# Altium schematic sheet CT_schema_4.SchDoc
size 395 x 205 mm
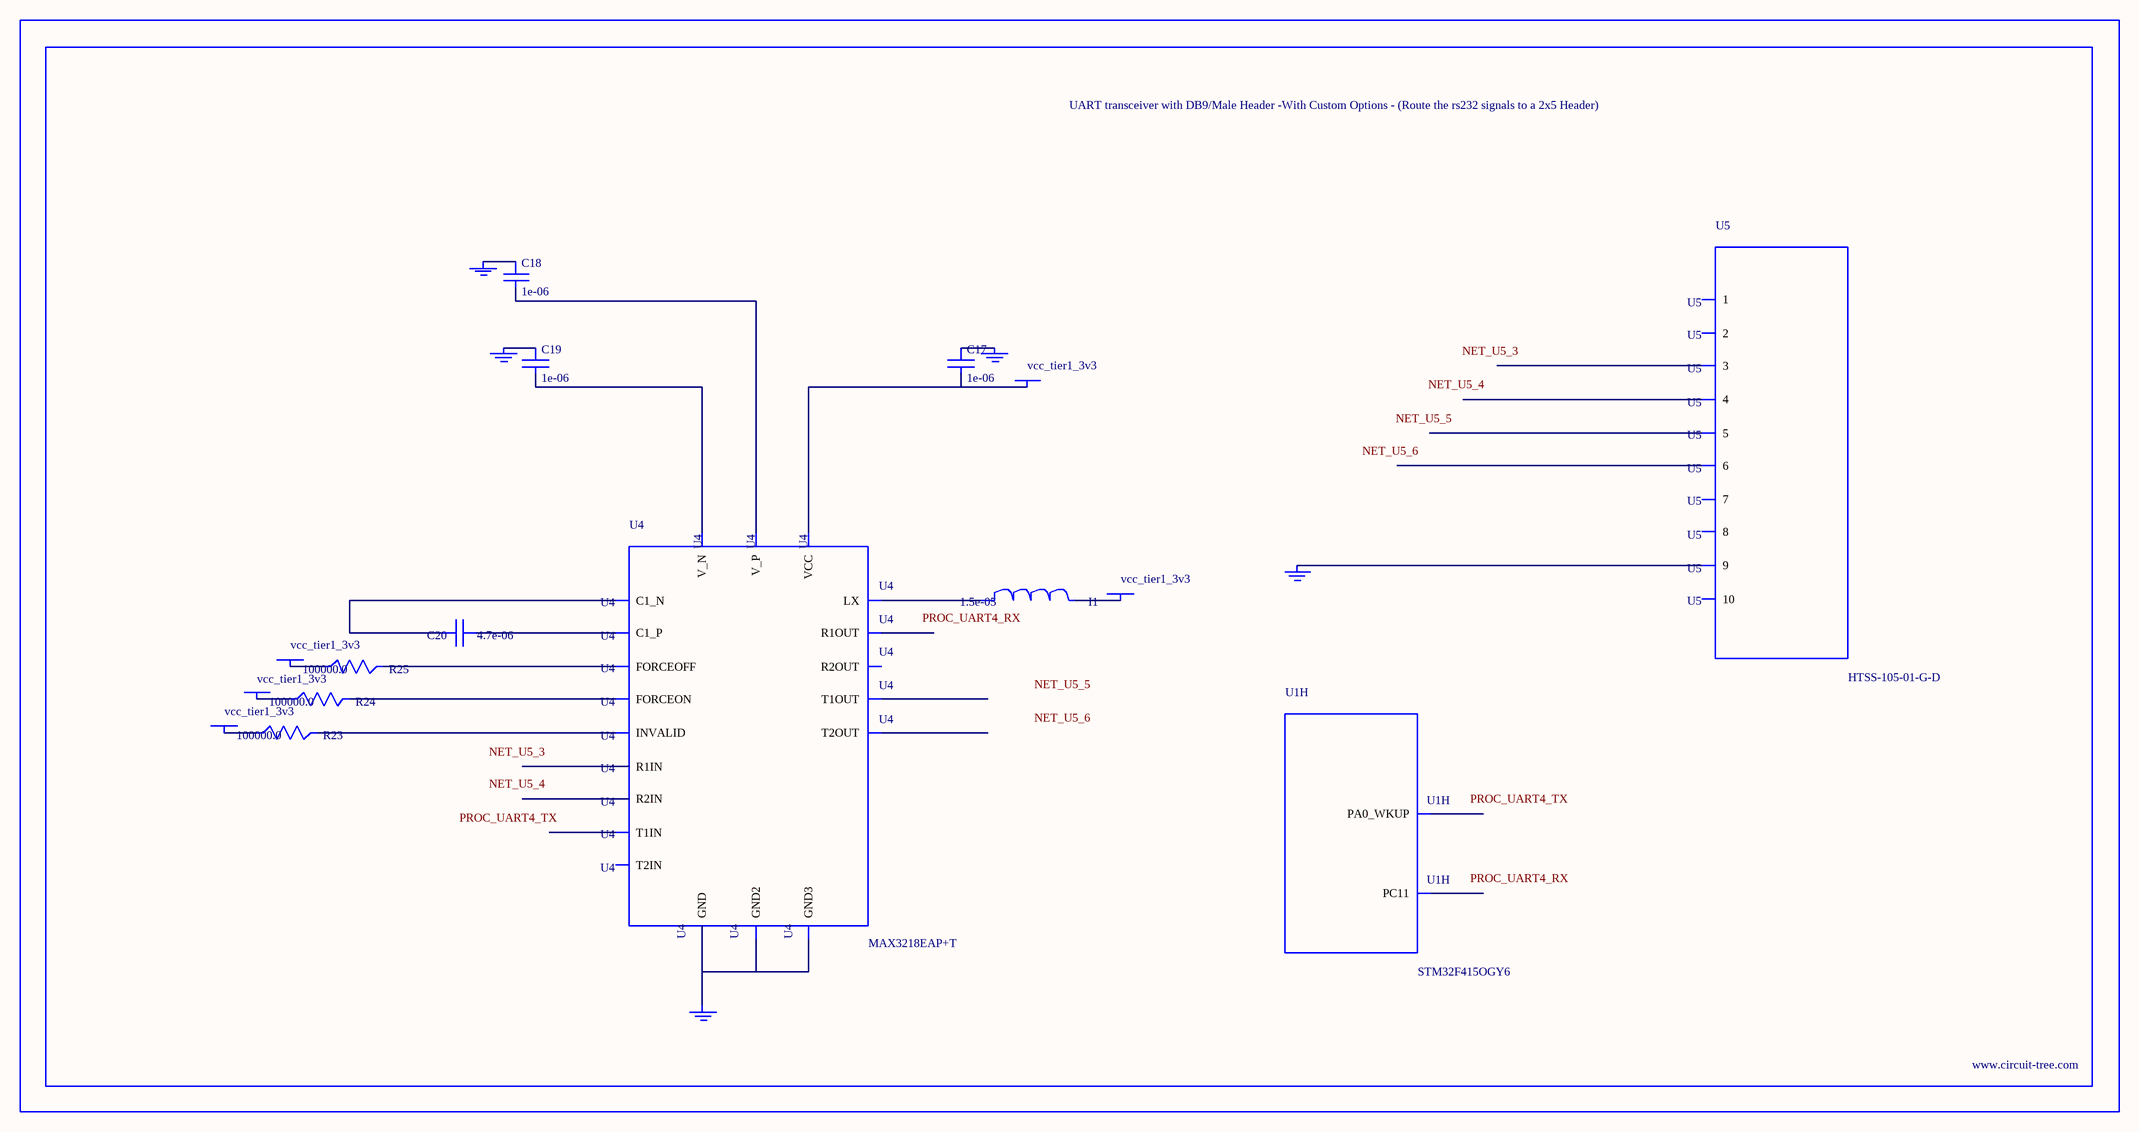
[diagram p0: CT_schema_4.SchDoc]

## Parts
BORDER3  (no value)
C17  1e-06  [C0603]
C18  1e-06  [C0603]
C19  1e-06  [C0603]
C20  4.7e-06  [C0805]
GND_INSTANCE_3_0  (no value)
GND_INSTANCE_3_1  (no value)
GND_INSTANCE_3_2  (no value)
GND_INSTANCE_3_3  (no value)
GND_INSTANCE_3_4  (no value)
I1  1.5e-05  [L1210]
POWER_INSTANCE_3_0  vcc_tier1_3v3
POWER_INSTANCE_3_1  vcc_tier1_3v3
POWER_INSTANCE_3_2  vcc_tier1_3v3
POWER_INSTANCE_3_3  vcc_tier1_3v3
POWER_INSTANCE_3_4  vcc_tier1_3v3
R23  100000.0  [R0603]
R24  100000.0  [R0603]
R25  100000.0  [R0603]
U1  STM32F415OGY6  [WLCSP90]  (part H of 9)
U4  MAX3218EAP+T  [SSOP-20]
U5  HTSS-105-01-G-D  [HTSS-105-01-G-D]

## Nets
NetC17_1: C17.1 GND_INSTANCE_3_0.0(GND)
NetC17_2: C17.2 POWER_INSTANCE_3_4.0(PWR) U4.6(VCC)
NetC18_1: C18.1 GND_INSTANCE_3_2.0(GND)
NetC18_2: C18.2 U4.19(V_P)
NetC19_1: C19.1 GND_INSTANCE_3_1.0(GND)
NetC19_2: C19.2 U4.15(V_N)
NetC20_1: C20.1 U4.18(C1_P)
NetC20_2: C20.2 U4.16(C1_N)
NetGND_INSTANCE_3_3_0: GND_INSTANCE_3_3.0(GND) U4.5(GND) U4.17(GND2) U4.20(GND3)
NetGND_INSTANCE_3_4_0: GND_INSTANCE_3_4.0(GND) U5.9
NetI1_1: I1.1 U4.1(LX)
NetI1_2: I1.2 POWER_INSTANCE_3_0.0(PWR)
NetPOWER_INSTANCE_3_1_0: POWER_INSTANCE_3_1.0(PWR) R23.1
NetPOWER_INSTANCE_3_2_0: POWER_INSTANCE_3_2.0(PWR) R24.1
NetPOWER_INSTANCE_3_3_0: POWER_INSTANCE_3_3.0(PWR) R25.1
NetR23_2: R23.2 U4.2(INVALID)
NetR24_2: R24.2 U4.3(FORCEON)
NetR25_2: R25.2 U4.4(FORCEOFF)

Not connected (* = marked no-connect by the designer): U1 C4(PC11) C10(PA0_WKUP); U4 7(T1IN) 8(T2IN) 9(R1OUT) 10(R2OUT) 11(R2IN) 12(R1IN) 13(T2OUT) 14(T1OUT); U5 1 2 3 4 5 6 7 8 10

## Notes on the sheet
- Labels drawn without touching a wire or pin: NET_U5_3, NET_U5_4, NET_U5_5, NET_U5_6, PROC_UART4_RX, PROC_UART4_TX

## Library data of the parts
BORDER3 = BORDER_PAGE3
C17-C19 = C0603C105K3RACTU
C20 = C0805C475K4RACTU
GND_INSTANCE_3_0-GND_INSTANCE_3_4 = GND
I1 = L1210R150MDWIT
POWER_INSTANCE_3_0-POWER_INSTANCE_3_4 = PWR
R23-R25 = RC0603JR-07100KL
